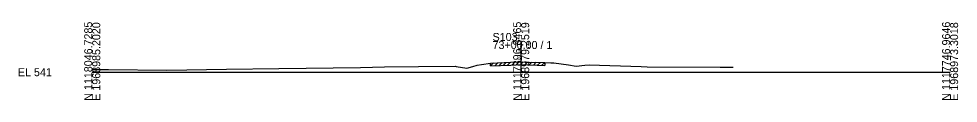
# Model space of a CAD drawing. Extents: x 974 to 1303, y 990 to 14518.
# Drawn here: x 974.3 to 1302.8, y 12990.3 to 13017.5 of the extents above; entities that cross this region are included whole.
import ezdxf

# ---------------------------------------------------------------- set-up
doc = ezdxf.new("R2010")
doc.units = 0
for name, color, linetype in [('Level 10', 7, 'Continuous'), ('Level 60', 7, 'Continuous'), ('Level 61', 7, 'Continuous'), ('Level 63', 7, 'Continuous')]:
    doc.layers.add(name, color=color, linetype=linetype)

msp = doc.modelspace()

# ---------------------------------------------------------------- linework, layer by layer
at = {"layer": 'Level 60'}
for p, q in [((1139.26, 13003.19), (1146.42, 13003.49)), ((1146.42, 13003.49), (1150.06, 13003.64)), ((1150.06, 13003.64), (1152.83, 13003.55)), ((1152.83, 13003.55), (1158.27, 13003.39)), ((1158.27, 13003.39), (1160.33, 13003.32)), ((1000, 13000.96), (1005.69, 13000.94)), ((1005.69, 13000.94), (1026.13, 13000.72)), ((1026.13, 13000.72), (1046.99, 13001.02)), ((1046.99, 13001.02), (1065.29, 13001.31)), ((1065.29, 13001.31), (1093.84, 13001.68)), ((1093.84, 13001.68), (1102.19, 13001.85)), ((1102.19, 13001.85), (1114.07, 13002)), ((1114.07, 13002), (1126.87, 13002.06)), ((1126.87, 13002.06), (1127.32, 13001.99)), ((1127.32, 13001.99), (1131.01, 13001.38)), ((1131.01, 13001.38), (1133.14, 13002.03)), ((1133.14, 13002.03), (1134.57, 13002.45)), ((1134.57, 13002.45), (1136.11, 13002.69)), ((1136.11, 13002.69), (1139.26, 13003.19)), ((1160.33, 13003.32), (1161.43, 13003.27)), ((1161.43, 13003.27), (1166.53, 13002.53)), ((1166.53, 13002.53), (1169.25, 13002.13)), ((1169.25, 13002.13), (1172.29, 13002.44)), ((1172.29, 13002.44), (1173.8, 13002.6)), ((1173.8, 13002.6), (1191.99, 13001.98)), ((1191.99, 13001.98), (1194.04, 13001.92)), ((1194.04, 13001.92), (1219.6, 13001.8)), ((1219.6, 13001.8), (1224.17, 13001.73))]:
    msp.add_line(p, q, dxfattribs=at)
at = {"layer": 'Level 61'}
for p, q in [((1142.26, 13002.32), (1143.3, 13003.36)), ((1143.76, 13002.38), (1144.8, 13003.43)), ((1145.26, 13002.45), (1146.3, 13003.49)), ((1146.76, 13002.51), (1147.8, 13003.55)), ((1148.26, 13002.57), (1149.3, 13003.61)), ((1149.76, 13002.63), (1150.75, 13003.62)), ((1151.26, 13002.61), (1152.23, 13003.57)), ((1152.76, 13002.56), (1153.73, 13003.53)), ((1154.26, 13002.51), (1155.23, 13003.48)), ((1155.76, 13002.46), (1156.73, 13003.43)), ((1157.26, 13002.42), (1158.23, 13003.39)), ((1158.27, 13003.39), (1158.27, 13002.39)), ((1139.26, 13002.19), (1140.3, 13003.23)), ((1139.26, 13002.19), (1139.26, 13003.19)), ((1139.26, 13002.19), (1146.42, 13002.49)), ((1139.26, 13002.19), (1139.26, 13002.19)), ((1140.76, 13002.25), (1141.8, 13003.3)), ((1146.42, 13002.49), (1150.06, 13002.64)), ((1150.06, 13002.64), (1152.83, 13002.55)), ((1152.83, 13002.55), (1158.27, 13002.39))]:
    msp.add_line(p, q, dxfattribs=at)
at = {"layer": 'Level 63'}
for p, q in [((1150, 13000), (1150, 13010.93)), ((1000, 13000), (1150, 13000)), ((1150, 13000), (1300, 13000))]:
    msp.add_line(p, q, dxfattribs=at)

# ---------------------------------------------------------------- texts
at = {"layer": 'Level 10'}
msp.add_text('544.64', height=0.9, rotation=90, dxfattribs=at).set_placement((1149.95, 13004.14))
at = {"layer": 'Level 63'}
for s, p in [('N 1118046.7285', (1000, 12990)), ('E 1968985.2020', (1002.8, 12990)), ('N 1117896.8465', (1150, 12990)), ('E 1968979.2519', (1152.8, 12990)), ('N 1117746.9646', (1300, 12990)), ('E 1968973.3018', (1302.8, 12990))]:
    msp.add_text(s, height=2.8, rotation=90, dxfattribs=at).set_placement(p)
for s, p in [('S103', (1140, 13010.93)), ('73+00.00 / 1', (1140, 13008.13)), ('EL 541', (974, 12998.6))]:
    msp.add_text(s, height=2.8, dxfattribs=at).set_placement(p)

doc.saveas('drawing.dxf')
